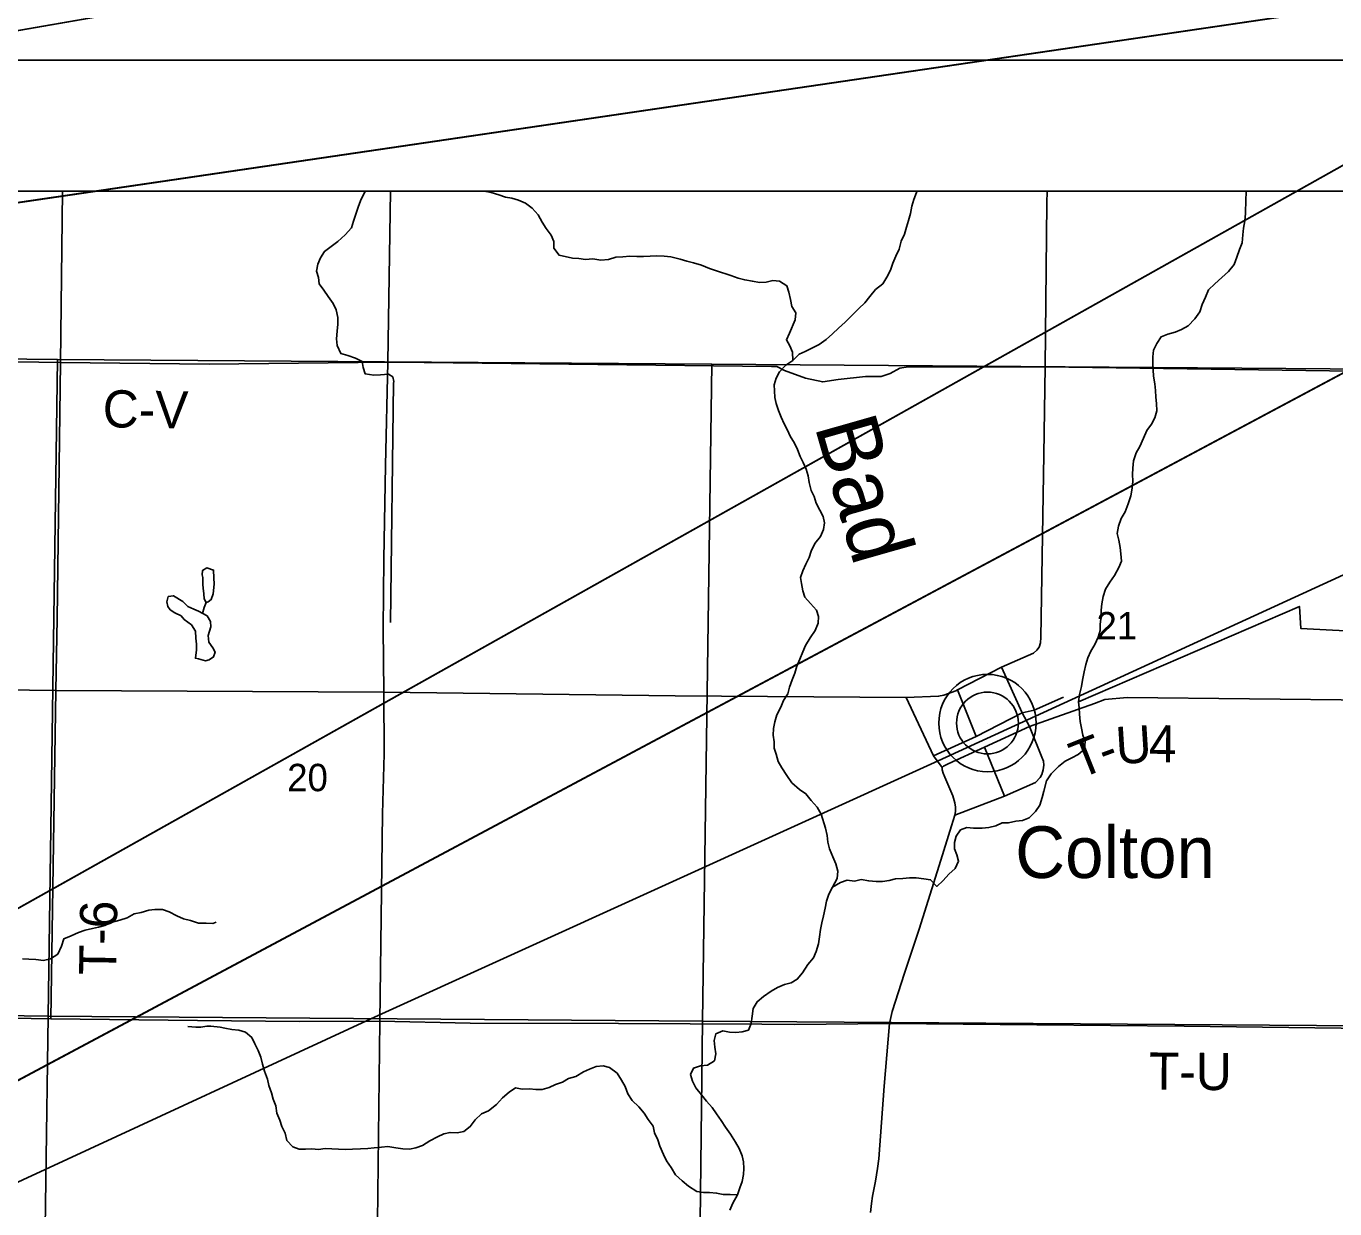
# Model space of a CAD drawing. Extents: x -6.2 to 37.4, y 0.2 to 22.2.
# Drawn here: x 7.359 to 8.359, y 20.33 to 21.233 of the extents above; entities that cross this region are included whole.
import ezdxf

# ---------------------------------------------------------------- set-up
doc = ezdxf.new("R2010")
doc.units = 0
for name, color, linetype in [('GM_X_County_Road', 7, 'Continuous'), ('GM_X_County_Road_Text', 7, 'Continuous'), ('GM_X_Minor_Lake', 7, 'Continuous'), ('GM_X_Minor_River', 7, 'Continuous'), ('GM_X_Minor_River_Text', 7, 'Continuous'), ('GM_X_Rail_Line', 7, 'Continuous'), ('GM_X_Section', 7, 'Continuous'), ('GM_X_Section_Text', 7, 'Continuous'), ('GM_X_Township_Road', 7, 'Continuous'), ('GM_X_Township_Road_Text', 7, 'Continuous'), ('GM_X_Unincorporated', 7, 'Continuous'), ('GM_X_Unincorporated_Location', 7, 'Continuous'), ('GM_X_Unincorporated_Text', 7, 'Continuous'), ('SH_Border', 7, 'Continuous'), ('SH_Data', 7, 'Continuous')]:
    doc.layers.add(name, color=color, linetype=linetype)

msp = doc.modelspace()

# ---------------------------------------------------------------- linework, layer by layer
at = {"layer": 'GM_X_County_Road'}
msp.add_line((8.0911, 20.6825), (8.1254, 20.6984), dxfattribs=at)
for points in [[(8.1254, 20.6984), (8.1199, 20.7088), (8.1041, 20.7438), (8.1286, 20.7545), (8.131, 20.7566), (8.1327, 20.7589), (8.1338, 20.7624), (8.1342, 20.7663), (8.1363, 20.9063), (8.1373, 20.9732), (8.1388, 21.0983), (8.139, 21.1074)], [(6.8905, 20.9813), (7.1711, 20.9799), (7.385, 20.9764)], [(7.385, 20.9764), (7.4985, 20.9753), (7.6352, 20.9767), (7.6629, 20.9765), (7.9284, 20.9735), (7.9324, 20.9733), (7.9382, 20.9704), (7.9543, 20.9645), (7.9675, 20.9617), (7.9791, 20.9635), (8.0001, 20.9657), (8.0121, 20.9659), (8.0189, 20.9681), (8.0264, 20.9722), (8.0328, 20.9731), (8.1373, 20.9732), (8.3908, 20.9695), (8.4085, 20.9693), (8.4809, 20.9685)], [(8.0587, 20.6671), (8.0598, 20.668), (8.0633, 20.6698), (8.0911, 20.6825)], [(8.0039, 20.3269), (8.0046, 20.3339), (8.0055, 20.3396), (8.0077, 20.351), (8.0092, 20.3606), (8.0102, 20.3679), (8.0145, 20.4236), (8.0184, 20.4715), (8.0206, 20.4805), (8.0299, 20.5099), (8.041, 20.5435), (8.0578, 20.5962), (8.0658, 20.6224), (8.0684, 20.6306), (8.0688, 20.6334), (8.069, 20.6368), (8.0685, 20.64), (8.0669, 20.6455), (8.0607, 20.6597), (8.0594, 20.6628), (8.0587, 20.6653), (8.0587, 20.6671)]]:
    msp.add_lwpolyline(points, dxfattribs=at)
at = {"layer": 'GM_X_Minor_Lake'}
for p, q in [((7.4937, 20.8123), (7.4938, 20.8068)), ((7.4724, 20.7851), (7.4773, 20.783))]:
    msp.add_line(p, q, dxfattribs=at)
for points in [[(7.4938, 20.8068), (7.4941, 20.804), (7.4944, 20.7998), (7.4947, 20.796), (7.4964, 20.7931), (7.4979, 20.7935), (7.5002, 20.7953), (7.5016, 20.7997), (7.5023, 20.807), (7.5022, 20.812), (7.5019, 20.8179), (7.4967, 20.8195), (7.4936, 20.8176), (7.4933, 20.8142), (7.4937, 20.8123)], [(7.4773, 20.783), (7.4795, 20.7801), (7.4851, 20.776), (7.4881, 20.7712), (7.4885, 20.7659), (7.4888, 20.7612), (7.4888, 20.757), (7.4881, 20.7505), (7.4904, 20.7501), (7.4958, 20.7485), (7.4987, 20.7492), (7.5019, 20.7515), (7.5031, 20.7552), (7.5013, 20.7585), (7.4983, 20.7629), (7.4979, 20.7678), (7.4999, 20.7746), (7.4996, 20.7786), (7.497, 20.783), (7.4904, 20.7864), (7.4868, 20.7881), (7.4823, 20.7901), (7.4784, 20.7938), (7.4713, 20.7983), (7.4673, 20.7976), (7.4663, 20.7936), (7.4671, 20.79), (7.4688, 20.7875), (7.4724, 20.7851)], [(7.4936, 20.7847), (7.4948, 20.7893), (7.4964, 20.7931)]]:
    msp.add_lwpolyline(points, dxfattribs=at)
at = {"layer": 'GM_X_Minor_River'}
for points in [[(7.618, 21.1074), (7.6176, 21.1065), (7.6146, 21.1013), (7.6128, 21.0958), (7.6089, 21.0845), (7.6073, 21.0794), (7.6024, 21.0741), (7.5968, 21.0689), (7.5917, 21.0652), (7.5868, 21.0613), (7.5837, 21.0564), (7.5816, 21.0515), (7.5805, 21.0462), (7.582, 21.0414), (7.5826, 21.0367), (7.5862, 21.0317), (7.5895, 21.0269), (7.5934, 21.0215), (7.5956, 21.0167), (7.5968, 21.0108), (7.5969, 21.0057), (7.5964, 21.0004), (7.5959, 20.9945), (7.5964, 20.9894), (7.5992, 20.9833), (7.6046, 20.9817), (7.6103, 20.9799), (7.6156, 20.9773), (7.6162, 20.9726), (7.6179, 20.9678), (7.6245, 20.9667), (7.6296, 20.967), (7.6355, 20.9675), (7.6388, 20.9654), (7.6396, 20.9619), (7.6395, 20.9608)], [(7.9445, 20.9781), (7.9444, 20.9844), (7.9424, 20.9891), (7.9397, 20.9939), (7.942, 20.999), (7.9464, 21.0092), (7.947, 21.0145), (7.9439, 21.0193), (7.9427, 21.0246), (7.9414, 21.0303), (7.94, 21.0351), (7.9344, 21.0386), (7.9293, 21.0392), (7.9241, 21.0378), (7.9192, 21.0377), (7.9137, 21.0385), (7.9078, 21.0396), (7.9029, 21.041), (7.8971, 21.043), (7.8862, 21.0466), (7.8809, 21.0484), (7.8749, 21.0508), (7.8688, 21.0526), (7.8637, 21.0538), (7.8586, 21.0554), (7.8513, 21.0572), (7.8463, 21.0577), (7.8405, 21.0579), (7.8355, 21.0578), (7.8304, 21.0575), (7.8255, 21.0574), (7.82, 21.0577), (7.8147, 21.0572), (7.8094, 21.0569), (7.8036, 21.0553), (7.7978, 21.0547), (7.7917, 21.0557), (7.7862, 21.0552), (7.7811, 21.0559), (7.7762, 21.0563), (7.766, 21.0584), (7.7619, 21.0638), (7.762, 21.0689), (7.7598, 21.0737), (7.7561, 21.0789), (7.7531, 21.0838), (7.75, 21.0894), (7.7455, 21.0944), (7.7403, 21.0983), (7.735, 21.1004), (7.7299, 21.102), (7.725, 21.1029), (7.7199, 21.1045), (7.7141, 21.1063), (7.7087, 21.1074)], [(8.033, 21.085), (8.0344, 21.0903), (8.0356, 21.096), (8.037, 21.1011), (8.039, 21.1064), (8.0395, 21.1074)], [(8.115, 20.626), (8.1201, 20.6265), (8.1251, 20.6285), (8.1299, 20.6334), (8.1334, 20.6382), (8.135, 20.6441), (8.1363, 20.649), (8.1385, 20.6568), (8.142, 20.6622), (8.1476, 20.6678), (8.1526, 20.6719), (8.1577, 20.6743), (8.1627, 20.6769), (8.1675, 20.6811), (8.168, 20.687), (8.1662, 20.6918), (8.1651, 20.6971), (8.1641, 20.7021), (8.1636, 20.7078), (8.1633, 20.7125), (8.1628, 20.7173), (8.1637, 20.7228), (8.1651, 20.7288), (8.166, 20.7337), (8.1672, 20.7402), (8.1686, 20.7458), (8.1699, 20.7509), (8.1722, 20.7558), (8.1753, 20.7611), (8.1779, 20.7667), (8.1795, 20.7716), (8.1794, 20.7766), (8.1802, 20.7824), (8.1801, 20.7872), (8.1808, 20.7921), (8.1816, 20.7978), (8.1834, 20.8033), (8.1868, 20.8087), (8.1903, 20.8136), (8.1938, 20.8198), (8.1958, 20.8247), (8.1953, 20.8302), (8.1948, 20.8352), (8.1936, 20.8407), (8.1925, 20.8458), (8.1934, 20.8513), (8.1954, 20.8572), (8.1985, 20.8624), (8.2007, 20.8686), (8.2029, 20.8745), (8.2039, 20.8804), (8.2044, 20.8858), (8.2041, 20.891), (8.2044, 20.8957), (8.205, 20.9014), (8.207, 20.9074), (8.2098, 20.9123), (8.2125, 20.9187), (8.2151, 20.9244), (8.2186, 20.9293), (8.2213, 20.9343), (8.2227, 20.9396), (8.2226, 20.9451), (8.222, 20.9501), (8.2217, 20.9552), (8.2212, 20.9603), (8.2203, 20.966), (8.2199, 20.9708), (8.2198, 20.9757), (8.2198, 20.9809), (8.2203, 20.9858), (8.2227, 20.9911), (8.226, 20.9961), (8.2311, 20.9981), (8.2368, 20.9997), (8.2416, 21.0018), (8.2466, 21.0045), (8.2518, 21.0099), (8.2555, 21.0152), (8.2573, 21.0208), (8.2599, 21.0265), (8.2622, 21.032), (8.2671, 21.0366), (8.2724, 21.0415), (8.2775, 21.0461), (8.2817, 21.0514), (8.2839, 21.0569), (8.2859, 21.0627), (8.2879, 21.068), (8.2884, 21.0739), (8.289, 21.0792), (8.2899, 21.0848), (8.2905, 21.0903), (8.2907, 21.101), (8.291, 21.1061), (8.2909, 21.1074)], [(7.9748, 20.5755), (7.9784, 20.5821), (7.979, 20.5879), (7.9774, 20.5933), (7.9752, 20.5987), (7.9727, 20.605), (7.9714, 20.6101), (7.9709, 20.6151), (7.9695, 20.6206), (7.9663, 20.6313), (7.9632, 20.6368), (7.9587, 20.6418), (7.9546, 20.647), (7.9497, 20.6501), (7.9439, 20.6552), (7.9399, 20.6609), (7.9362, 20.6667), (7.9334, 20.6716), (7.9318, 20.6772), (7.9304, 20.6819), (7.9303, 20.6867), (7.9296, 20.6918), (7.9299, 20.6967), (7.9309, 20.702), (7.9323, 20.7073), (7.9353, 20.7132), (7.9374, 20.7182), (7.9407, 20.7233), (7.942, 20.7284), (7.944, 20.7339), (7.9461, 20.7392), (7.9477, 20.7445), (7.9499, 20.7499), (7.9523, 20.7554), (7.9543, 20.7603), (7.9578, 20.7661), (7.9617, 20.7716), (7.964, 20.7772), (7.9641, 20.7825), (7.9627, 20.7873), (7.9582, 20.7923), (7.9538, 20.7971), (7.9521, 20.8021), (7.9511, 20.8076), (7.9504, 20.8123), (7.9522, 20.8174), (7.9546, 20.8223), (7.9571, 20.8274), (7.9587, 20.8323), (7.9615, 20.8382), (7.9657, 20.8436), (7.9679, 20.8489), (7.9689, 20.854), (7.9677, 20.8589), (7.9651, 20.8637), (7.9624, 20.8691), (7.9608, 20.874), (7.9586, 20.8788), (7.957, 20.8847), (7.9563, 20.89), (7.9547, 20.895), (7.9525, 20.9), (7.9503, 20.9047), (7.9481, 20.9099), (7.9459, 20.9149), (7.9426, 20.9201), (7.9406, 20.9248), (7.938, 20.9296), (7.9356, 20.9348), (7.9336, 20.9397), (7.9318, 20.9451), (7.9308, 20.9498), (7.9305, 20.9548), (7.9304, 20.9595), (7.9318, 20.9644), (7.9343, 20.9693), (7.9393, 20.9744), (7.9445, 20.9781), (7.9493, 20.9828), (7.9541, 20.985), (7.9595, 20.9877), (7.9646, 20.9903), (7.97, 20.994), (7.9748, 20.9983), (7.9796, 21.0028), (7.9846, 21.0072), (7.99, 21.0126), (7.9949, 21.0177), (7.9997, 21.022), (8.0034, 21.027), (8.0078, 21.0323), (8.0134, 21.0366), (8.0163, 21.0416), (8.0193, 21.0471), (8.0209, 21.0524), (8.0234, 21.0578), (8.0258, 21.0631), (8.0274, 21.0693), (8.0298, 21.0746), (8.0314, 21.0799), (8.033, 21.085)], [(7.6395, 20.9608), (7.6372, 20.7777)], [(8.1628, 20.7173), (8.3317, 20.7901), (8.3327, 20.7733), (8.3863, 20.7704)], [(7.8965, 20.3287), (7.8988, 20.3341), (7.9024, 20.3405), (7.9042, 20.3458), (7.9059, 20.3507), (7.9068, 20.356), (7.9071, 20.3607), (7.9068, 20.3657), (7.9059, 20.3704), (7.9037, 20.376), (7.9008, 20.3808), (7.8969, 20.3869), (7.8932, 20.3923), (7.8897, 20.3974), (7.8863, 20.4024), (7.883, 20.4072), (7.8786, 20.412), (7.8747, 20.417), (7.8704, 20.4222), (7.8678, 20.4274), (7.8664, 20.4325), (7.8686, 20.4374), (7.8741, 20.439), (7.8794, 20.4395), (7.8848, 20.4429), (7.8858, 20.4483), (7.8849, 20.4533), (7.8845, 20.4584), (7.8857, 20.4635), (7.8912, 20.4657), (7.8963, 20.4647), (7.9011, 20.4646), (7.9058, 20.4651), (7.9106, 20.4663), (7.9127, 20.4714), (7.9134, 20.4771), (7.9143, 20.4828), (7.9174, 20.4881), (7.9222, 20.4921), (7.9281, 20.4962), (7.9329, 20.499), (7.9381, 20.5012), (7.9432, 20.5024), (7.948, 20.5052), (7.9519, 20.5101), (7.956, 20.5165), (7.9604, 20.5215), (7.9624, 20.5264), (7.9642, 20.5323), (7.9649, 20.5376), (7.9657, 20.5432), (7.9668, 20.5483), (7.968, 20.5538), (7.9692, 20.5595), (7.9703, 20.565), (7.9721, 20.5703), (7.9748, 20.5755), (7.9809, 20.5792), (7.9861, 20.5809), (7.9918, 20.5802), (7.9967, 20.5814), (8.0026, 20.5804), (8.0083, 20.5799), (8.013, 20.58), (8.0181, 20.5807), (8.0231, 20.582), (8.0286, 20.5821), (8.0337, 20.5826), (8.0388, 20.5827), (8.0447, 20.582), (8.0498, 20.5812), (8.0546, 20.5761), (8.0595, 20.5806), (8.0637, 20.5855), (8.0687, 20.5898), (8.0713, 20.5954), (8.0698, 20.6002), (8.068, 20.605), (8.0681, 20.6097), (8.0695, 20.6146), (8.0728, 20.6195), (8.0776, 20.6211), (8.0827, 20.6207), (8.0893, 20.6207), (8.0943, 20.6212), (8.0998, 20.6225), (8.1046, 20.6247), (8.1093, 20.6248), (8.115, 20.626)], [(7.356, 20.5208), (7.3609, 20.5205), (7.366, 20.5203), (7.3721, 20.5196), (7.3774, 20.5208), (7.383, 20.5244), (7.3857, 20.5306), (7.3875, 20.536), (7.3931, 20.5384), (7.3988, 20.541), (7.4038, 20.5428), (7.4093, 20.544), (7.414, 20.5449), (7.4188, 20.5464), (7.4238, 20.5486), (7.4303, 20.5503), (7.4358, 20.5522), (7.4413, 20.5553), (7.4467, 20.5562), (7.4524, 20.558), (7.4571, 20.5586), (7.4628, 20.5584), (7.4681, 20.5568), (7.4739, 20.5538), (7.479, 20.5515), (7.4843, 20.55), (7.4903, 20.5482), (7.4964, 20.5481), (7.5013, 20.5479), (7.5038, 20.5488)], [(7.9024, 20.3405), (7.8967, 20.3408), (7.8914, 20.3407), (7.8863, 20.3419), (7.881, 20.3422), (7.8762, 20.3423), (7.8713, 20.3431), (7.8649, 20.3472), (7.8601, 20.3511), (7.8548, 20.3559), (7.8517, 20.3614), (7.848, 20.3666), (7.8458, 20.3714), (7.8429, 20.3777), (7.8413, 20.3825), (7.8389, 20.388), (7.8378, 20.393), (7.8341, 20.3981), (7.831, 20.4029), (7.8269, 20.4077), (7.8217, 20.4126), (7.8186, 20.4177), (7.8164, 20.4233), (7.8136, 20.4282), (7.8103, 20.4334), (7.8045, 20.4377), (7.7996, 20.4391), (7.7943, 20.4386), (7.7893, 20.4366), (7.7845, 20.4344), (7.7788, 20.4309), (7.7732, 20.4293), (7.7685, 20.4267), (7.7631, 20.4249), (7.7583, 20.4225), (7.753, 20.4209), (7.7483, 20.421), (7.7433, 20.4214), (7.7378, 20.4213), (7.7327, 20.4222), (7.7279, 20.419), (7.7228, 20.4145), (7.7181, 20.4095), (7.712, 20.4048), (7.7068, 20.4023), (7.7018, 20.3978), (7.6981, 20.3927), (7.6931, 20.3888), (7.688, 20.388), (7.6827, 20.3882), (7.6779, 20.387), (7.673, 20.3848), (7.6672, 20.3818), (7.6617, 20.3781), (7.6565, 20.3765), (7.6516, 20.3755), (7.6466, 20.3757), (7.6413, 20.3764), (7.6351, 20.3774), (7.6302, 20.3769), (7.6247, 20.3763), (7.6199, 20.3758), (7.6142, 20.3757), (7.6081, 20.3754), (7.603, 20.3751), (7.5975, 20.3754), (7.5873, 20.3759), (7.582, 20.3752), (7.5771, 20.3757), (7.5721, 20.3754), (7.5674, 20.3755), (7.5625, 20.3771), (7.558, 20.3819), (7.5566, 20.3876), (7.554, 20.3926), (7.5526, 20.3975), (7.5504, 20.4029), (7.5494, 20.4084), (7.5474, 20.4136), (7.5461, 20.4185), (7.5441, 20.424), (7.5431, 20.4288), (7.5409, 20.4351), (7.5393, 20.4403), (7.5381, 20.4458), (7.5361, 20.4509), (7.5335, 20.4559), (7.5313, 20.4607), (7.5264, 20.4649), (7.5212, 20.4662), (7.5159, 20.4668), (7.5106, 20.4678), (7.5069, 20.4687), (7.4998, 20.4693), (7.4967, 20.4693), (7.4921, 20.4687), (7.4885, 20.4687), (7.4824, 20.4692)]]:
    msp.add_lwpolyline(points, dxfattribs=at)
at = {"layer": 'GM_X_Rail_Line'}
for points in [[(8.4809, 19.1054), (8.4809, 21.1074), (6.8924, 21.1074), (6.8904, 20.9816), (6.8845, 20.734), (6.8795, 20.4839), (6.8793, 20.4771), (6.8722, 20.0984), (6.8719, 20.072), (6.8703, 19.9789), (6.8701, 19.9755), (6.8681, 19.854), (6.8645, 19.7209), (6.8637, 19.6871), (6.861, 19.5138)], [(6.8073, 20.0983), (7.1241, 20.2447), (7.6221, 20.4751), (8.0556, 20.6721), (8.387, 20.8242), (8.4809, 20.8677)]]:
    msp.add_lwpolyline(points, dxfattribs=at)
at = {"layer": 'GM_X_Section'}
for points in [[(6.8897, 20.9842), (7.3828, 20.9787), (7.3756, 20.4769), (6.8783, 20.4838), (6.8897, 20.9824)], [(7.8827, 20.9753), (7.8755, 20.4732), (7.3756, 20.4769), (7.3828, 20.9787)], [(7.8827, 20.9753), (8.3887, 20.9715), (8.3809, 20.4697), (7.8755, 20.4732)], [(6.8783, 20.4838), (7.3756, 20.4769), (7.3685, 19.9738), (6.8683, 19.9802), (6.8784, 20.4793)], [(7.3756, 20.4769), (7.8755, 20.4732), (7.8696, 19.9699), (7.3685, 19.9738)], [(8.3809, 20.4697), (8.3809, 20.4674), (8.3737, 19.9673), (8.0032, 19.9691), (8.0005, 19.9689), (7.8696, 19.9699), (7.8755, 20.4732)]]:
    msp.add_lwpolyline(points, close=True, dxfattribs=at)
at = {"layer": 'GM_X_Township_Road'}
for p, q in [((7.385, 20.9764), (7.3866, 21.1074)), ((8.0704, 20.7263), (8.0847, 20.6907)), ((8.0911, 20.6825), (8.1254, 20.6984)), ((8.1063, 20.6452), (8.0911, 20.6825))]:
    msp.add_line(p, q, dxfattribs=at)
for points in [[(7.629, 20.4732), (7.6309, 20.6316), (7.6324, 20.6774), (7.6321, 20.7247), (7.6316, 20.7733), (7.632, 20.8261), (7.6333, 20.8977), (7.6352, 20.9767), (7.6372, 21.1074)], [(7.3775, 20.475), (7.3814, 20.7258), (7.3823, 20.7805), (7.385, 20.9764)], [(8.0313, 20.7204), (8.0559, 20.7215), (8.0599, 20.7222), (8.0691, 20.7257), (8.0704, 20.7263), (8.1041, 20.7438)], [(7.1081, 20.7293), (7.1101, 20.7293), (7.1793, 20.7284), (7.3814, 20.7258), (7.6321, 20.7247)], [(7.6321, 20.7247), (7.8547, 20.7218), (8.0313, 20.7204), (8.0521, 20.6759), (8.0587, 20.6671)], [(8.0521, 20.6759), (8.0847, 20.6907), (8.1199, 20.7088), (8.129, 20.7108), (8.1515, 20.7207)], [(8.1254, 20.6984), (8.1752, 20.7159), (8.1831, 20.7189), (8.2001, 20.7204), (8.3869, 20.7184)], [(8.1358, 20.6652), (8.1365, 20.6688), (8.1361, 20.6719), (8.1348, 20.675), (8.1254, 20.6984)], [(8.0587, 20.6671), (8.0598, 20.668), (8.0633, 20.6698), (8.0911, 20.6825)], [(8.0684, 20.6306), (8.1063, 20.6452), (8.1299, 20.6555), (8.1335, 20.6593), (8.1349, 20.6617), (8.1358, 20.6652)], [(6.8796, 20.4836), (6.9964, 20.481), (7.1268, 20.4799), (7.2567, 20.4771), (7.3775, 20.475)], [(7.3775, 20.475), (7.4897, 20.4738), (7.5676, 20.4729), (7.629, 20.4732), (7.6979, 20.4718), (7.8114, 20.4713), (7.921, 20.4708), (7.9458, 20.4707), (8.0184, 20.4715), (8.2437, 20.4694), (8.3835, 20.4677)], [(7.6248, 19.9695), (7.6255, 20.0382), (7.6263, 20.1111), (7.6272, 20.3198), (7.629, 20.4732)]]:
    msp.add_lwpolyline(points, dxfattribs=at)
at = {"layer": 'GM_X_Unincorporated'}
for radius in [0.0372, 0.0236]:
    msp.add_circle((8.0933, 20.701), radius, dxfattribs=at)
at = {"layer": 'GM_X_Unincorporated_Location'}
msp.add_line((8.0933, 20.701), (8.0933, 20.701), dxfattribs=at)
at = {"layer": 'SH_Border'}
for p, q in [((2.4693, 20.3804), (9.0866, 21.532)), ((2.4803, 17.8272), (9.0866, 21.532)), ((9.0866, 21.3538), (2.4693, 20.3804)), ((9.0866, 21.3538), (2.4803, 17.8272))]:
    msp.add_line(p, q, dxfattribs=at)
at = {"layer": 'SH_Data'}
for p, q in [((1.5809, 21.2074), (8.5809, 21.2074)), ((1.6809, 21.1074), (8.4809, 21.1074))]:
    msp.add_line(p, q, dxfattribs=at)
for points in [[(9.0866, 21.3538), (2.4693, 20.3804), (9.0866, 21.532)], [(9.0866, 21.3538), (2.4803, 17.8272), (9.0866, 21.532)]]:
    msp.add_lwpolyline(points, close=True, dxfattribs=at)

# ---------------------------------------------------------------- texts
at = {"layer": 'GM_X_County_Road_Text'}
msp.add_text('C-V', height=0.02841, rotation=359.2047, dxfattribs=at).set_placement((7.4171, 20.927))
at = {"layer": 'GM_X_Minor_River_Text'}
msp.add_text('Bad', height=0.04738, rotation=285.9142, dxfattribs=at).set_placement((7.961, 20.928))
at = {"layer": 'GM_X_Section_Text'}
for s, p in [('21', (8.1766, 20.7649)), ('20', (7.5582, 20.6489))]:
    msp.add_text(s, height=0.02093, rotation=0, dxfattribs=at).set_placement(p)
at = {"layer": 'GM_X_Township_Road_Text'}
for s, height, rotation, p in [('T', 0.0284, 21.6892, (8.1637, 20.6581)), ('U', 0.0284, 3.5868, (8.1921, 20.6695)), ('4', 0.0284, 359.4536, (8.2165, 20.6711)), ('-', 0.0284, 20.2198, (8.1833, 20.6659)), ('T-6', 0.02841, 89.0457, (7.4275, 20.5081)), ('T-U', 0.02841, 359.588, (8.2166, 20.4209))]:
    msp.add_text(s, height=height, rotation=rotation, dxfattribs=at).set_placement(p)
at = {"layer": 'GM_X_Unincorporated_Text'}
msp.add_text('Colton', height=0.03949, rotation=0, dxfattribs=at).set_placement((8.1145, 20.5826))

doc.saveas('drawing.dxf')
